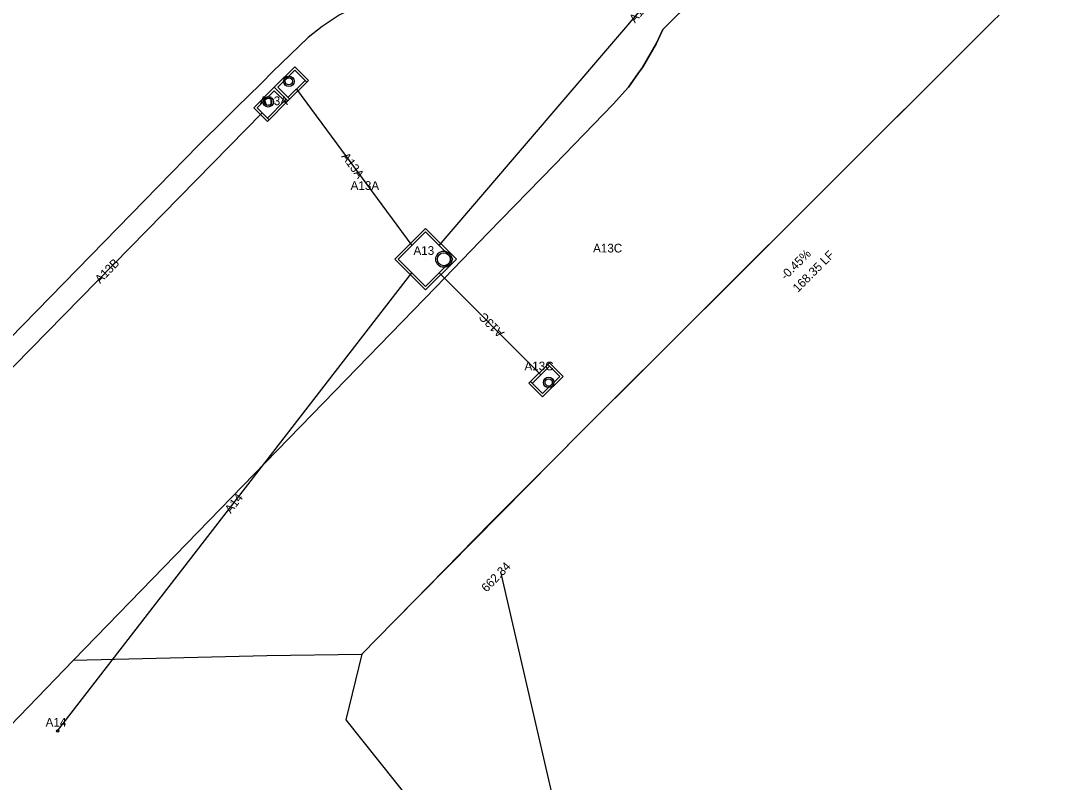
# Model space of a CAD drawing. Extents: x 2252703 to 2264864, y 13787568 to 13790989.
# Drawn here: x 2252893 to 2253106.1, y 13788691.8 to 13788849.4 of the extents above; entities that cross this region are included whole.
import ezdxf

# ---------------------------------------------------------------- set-up
doc = ezdxf.new("R2010")
doc.units = 0
for name, color, linetype in [('D_BOXES_1', 7, 'Continuous'), ('D_DRAIN_MISC', 7, 'Continuous'), ('D_DRAIN_NOTES_1', 7, 'Continuous'), ('D_DRN_AREA_X', 7, 'Continuous'), ('D_DRN_CHANNEL_FLOW', 7, 'Continuous'), ('D_DRN_SHALLOW_CONC_FLOW', 7, 'Continuous'), ('D_INLET_1', 7, 'Continuous'), ('D_MH_1', 7, 'Continuous'), ('D_PIPES_1', 7, 'Continuous')]:
    doc.layers.add(name, color=color, linetype=linetype)

msp = doc.modelspace()

# ---------------------------------------------------------------- linework, layer by layer
at = {"layer": 'D_BOXES_1'}
for p, q in [((2252979.56, 13788802.85), (2253062.33, 13788899.63)), ((2252900.7, 13788702.47), (2252973.9, 13788797.2))]:
    msp.add_line(p, q, dxfattribs=at)
at = {"layer": 'D_DRAIN_MISC'}
for p, q in [((2252947.95, 13788837.34), (2252947.95, 13788837.34)), ((2252950.78, 13788838.05), (2252950.78, 13788838.05)), ((2252946.88, 13788834.16), (2252946.88, 13788834.16)), ((2252950.07, 13788835.22), (2252950.07, 13788835.22)), ((2252943.7, 13788833.11), (2252943.7, 13788833.11)), ((2252942.99, 13788830.28), (2252942.99, 13788830.28)), ((2252945.82, 13788830.98), (2252945.82, 13788830.98)), ((2252973.9, 13788802.85), (2252973.9, 13788802.85)), ((2252979.56, 13788802.85), (2252979.56, 13788802.85)), ((2252976.73, 13788800.02), (2252976.73, 13788800.02)), ((2252973.9, 13788797.2), (2252973.9, 13788797.2)), ((2252979.56, 13788797.19), (2252979.56, 13788797.19)), ((2253003.41, 13788776.84), (2253003.41, 13788776.84)), ((2253000.58, 13788776.14), (2253000.58, 13788776.14)), ((2253001.64, 13788775.08), (2253001.64, 13788775.08)), ((2252999.87, 13788773.31), (2252999.87, 13788773.31)), ((2253002.7, 13788774.01), (2253002.7, 13788774.01))]:
    msp.add_line(p, q, dxfattribs=at)
at = {"layer": 'D_DRN_AREA_X'}
for p, q in [((2253025.74, 13788847.54), (2253047.63, 13788869.4)), ((2253047.63, 13788869.4), (2253025.74, 13788847.54)), ((2253091.64, 13788846.92), (2253094.09, 13788849.37)), ((2253094.09, 13788849.37), (2253095.25, 13788850.52)), ((2253024.38, 13788844.58), (2253025.74, 13788847.54)), ((2253025.74, 13788847.54), (2253024.38, 13788844.58)), ((2253090.84, 13788846.12), (2253091.64, 13788846.92)), ((2253021.56, 13788839.64), (2253024.38, 13788844.58)), ((2253024.38, 13788844.58), (2253021.56, 13788839.64)), ((2253087.3, 13788842.58), (2253090.84, 13788846.12)), ((2253018.99, 13788836.08), (2253020.76, 13788838.54)), ((2253020.76, 13788838.54), (2253018.99, 13788836.08)), ((2253020.76, 13788838.54), (2253021.56, 13788839.64)), ((2253021.56, 13788839.64), (2253020.76, 13788838.54)), ((2253018.66, 13788835.63), (2253018.99, 13788836.08)), ((2253018.99, 13788836.08), (2253018.66, 13788835.63)), ((2253015.52, 13788832.07), (2253018.66, 13788835.63)), ((2253018.66, 13788835.63), (2253015.52, 13788832.07)), ((2253003.36, 13788819.54), (2253015.52, 13788832.07)), ((2253015.52, 13788832.07), (2253003.36, 13788819.54)), ((2252989.7, 13788805.46), (2253003.36, 13788819.54)), ((2253003.36, 13788819.54), (2252989.7, 13788805.46)), ((2252978.83, 13788794.25), (2252989.7, 13788805.46)), ((2252989.7, 13788805.46), (2252978.83, 13788794.25)), ((2253045.82, 13788801.17), (2253048.68, 13788804.03)), ((2252978.83, 13788794.25), (2252953.29, 13788767.93)), ((2252953.29, 13788767.93), (2252946.01, 13788760.43)), ((2252903.98, 13788717.11), (2252946.01, 13788760.43)), ((2252946.01, 13788760.43), (2252903.98, 13788717.11)), ((2252990.18, 13788745.5), (2253003.58, 13788758.93)), ((2252974.41, 13788729.4), (2252990.18, 13788745.5)), ((2252903.98, 13788717.11), (2252943.92, 13788718.06)), ((2252943.92, 13788718.06), (2252963.58, 13788718.34))]:
    msp.add_line(p, q, dxfattribs=at)
for points in [[(2253012.64, 13788889.21), (2252992.46, 13788869.19), (2252988.07, 13788865.34), (2252984.21, 13788862.61), (2252965.2, 13788853.73), (2252958.91, 13788850.5), (2252955.35, 13788848.13), (2252952.47, 13788845.86), (2252945.11, 13788838.75), (2252942.89, 13788836.53), (2252939.85, 13788833.54), (2252938.06, 13788831.83), (2252935.45, 13788829.22), (2252929.84, 13788823.59), (2252874.02, 13788766.49), (2252881.47, 13788764.79), (2252887.1, 13788699.7), (2252903.98, 13788717.11)], [(2253094.09, 13788849.37), (2253090.84, 13788846.12), (2253060.74, 13788816.07), (2253008.83, 13788764.24), (2252970.16, 13788725.1), (2252963.58, 13788718.34)], [(2253048.68, 13788804.03), (2253060.74, 13788816.07), (2253087.3, 13788842.58)], [(2253003.58, 13788758.93), (2253008.83, 13788764.24), (2253022.74, 13788778.13), (2253045.82, 13788801.17)], [(2252946.01, 13788760.43), (2252953.29, 13788767.93), (2252978.83, 13788794.25)], [(2252963.58, 13788718.34), (2252970.16, 13788725.1), (2252974.41, 13788729.4)], [(2252963.58, 13788718.34), (2252960.26, 13788704.75), (2252988.05, 13788669.84)]]:
    msp.add_lwpolyline(points, dxfattribs=at)
at = {"layer": 'D_DRN_SHALLOW_CONC_FLOW'}
msp.add_line((2253106.06, 13788241.86), (2252992.29, 13788735.41), dxfattribs=at)
msp.add_line((2253106.06, 13788241.86), (2252992.29, 13788735.41), dxfattribs=at)
at = {"layer": 'D_INLET_1'}
for p, q in [((2252945.47, 13788835.58), (2252949.72, 13788839.82)), ((2252946.18, 13788835.58), (2252949.72, 13788839.11)), ((2252949.72, 13788839.82), (2252952.54, 13788836.99)), ((2252949.72, 13788839.11), (2252952.19, 13788836.63)), ((2252948.3, 13788832.75), (2252952.54, 13788836.99)), ((2252948.3, 13788833.46), (2252951.84, 13788836.99)), ((2252941.22, 13788831.34), (2252945.47, 13788835.58)), ((2252941.93, 13788831.34), (2252945.47, 13788834.87)), ((2252945.47, 13788835.58), (2252948.3, 13788832.75)), ((2252945.47, 13788835.58), (2252948.3, 13788832.75)), ((2252945.47, 13788835.58), (2252948.3, 13788832.75)), ((2252945.47, 13788835.58), (2252948.3, 13788832.75)), ((2252945.47, 13788834.87), (2252947.94, 13788832.4)), ((2252946.18, 13788835.58), (2252948.65, 13788833.1)), ((2252944.05, 13788828.51), (2252948.3, 13788832.75)), ((2252944.05, 13788829.22), (2252947.59, 13788832.75)), ((2252941.22, 13788831.34), (2252944.05, 13788828.51)), ((2252941.93, 13788831.34), (2252944.4, 13788828.86)), ((2252970.37, 13788800.03), (2252976.74, 13788806.39)), ((2252976.74, 13788806.39), (2252983.1, 13788800.02)), ((2252971.07, 13788800.03), (2252976.74, 13788805.68)), ((2252976.74, 13788805.68), (2252982.39, 13788800.02)), ((2252976.73, 13788793.66), (2252970.37, 13788800.03)), ((2252976.73, 13788794.36), (2252971.07, 13788800.03)), ((2252983.1, 13788800.02), (2252976.73, 13788793.66)), ((2252982.39, 13788800.02), (2252976.73, 13788794.36)), ((2253002.35, 13788778.61), (2252998.1, 13788774.37)), ((2253005.17, 13788775.78), (2253002.35, 13788778.61)), ((2253002.35, 13788777.9), (2252998.81, 13788774.37)), ((2253004.47, 13788775.78), (2253001.99, 13788778.26)), ((2253000.93, 13788771.54), (2252998.1, 13788774.37)), ((2253000.93, 13788772.25), (2252998.45, 13788774.73)), ((2253005.17, 13788775.78), (2253000.93, 13788771.54)), ((2253004.47, 13788775.78), (2253000.93, 13788772.25))]:
    msp.add_line(p, q, dxfattribs=at)
for centre, radius in [((2252948.48, 13788836.81), 1.08), ((2252948.48, 13788836.81), 0.75), ((2252944.23, 13788832.57), 1.08), ((2252944.23, 13788832.57), 0.75), ((2252980.5, 13788800.02), 1.67), ((2252980.5, 13788800.02), 1.33), ((2253002.17, 13788774.55), 1.08), ((2253002.17, 13788774.55), 0.75)]:
    msp.add_circle(centre, radius, dxfattribs=at)
at = {"layer": 'D_MH_1'}
msp.add_circle((2252900.7, 13788702.47), 0.25, dxfattribs=at)
at = {"layer": 'D_PIPES_1'}
for p, q in [((2252950.07, 13788835.22), (2252973.9, 13788802.85)), ((2252879.46, 13788765.62), (2252942.99, 13788830.28)), ((2253000.58, 13788776.14), (2252979.56, 13788797.19))]:
    msp.add_line(p, q, dxfattribs=at)

# ---------------------------------------------------------------- texts
at = {"layer": 'D_DRAIN_NOTES_1'}
for s, rotation, p in [('A13', 49.463, (2253020.01, 13788848.76)), ('A13A', 306.3701, (2252959.24, 13788821.25)), ('A13B', 45.5025, (2252909.47, 13788794.87)), ('A13C', 134.9537, (2252993.11, 13788784.89)), ('A14', 52.3044, (2252936.49, 13788747.31)), ('662.34', 46.1117, (2252989.36, 13788731.05))]:
    msp.add_text(s, height=1.8, rotation=rotation, dxfattribs=at).set_placement(p)
for s, p in [('A13A', (2252942.41, 13788831.88)), ('A13A', (2252961.24, 13788814.36)), ('A13', (2252974.23, 13788800.92)), ('A13C', (2253011.35, 13788801.42)), ('A13C', (2252997.17, 13788777.04)), ('A14', (2252898.21, 13788703.37))]:
    msp.add_text(s, height=1.8, dxfattribs=at).set_placement(p)
at = {"layer": 'D_DRN_CHANNEL_FLOW'}
for s, p in [('-0.45%', (2253051.14, 13788795.6)), ('168.35 LF', (2253053.68, 13788793.06))]:
    msp.add_text(s, height=1.8, rotation=45.0372, dxfattribs=at).set_placement(p)

doc.saveas('drawing.dxf')
